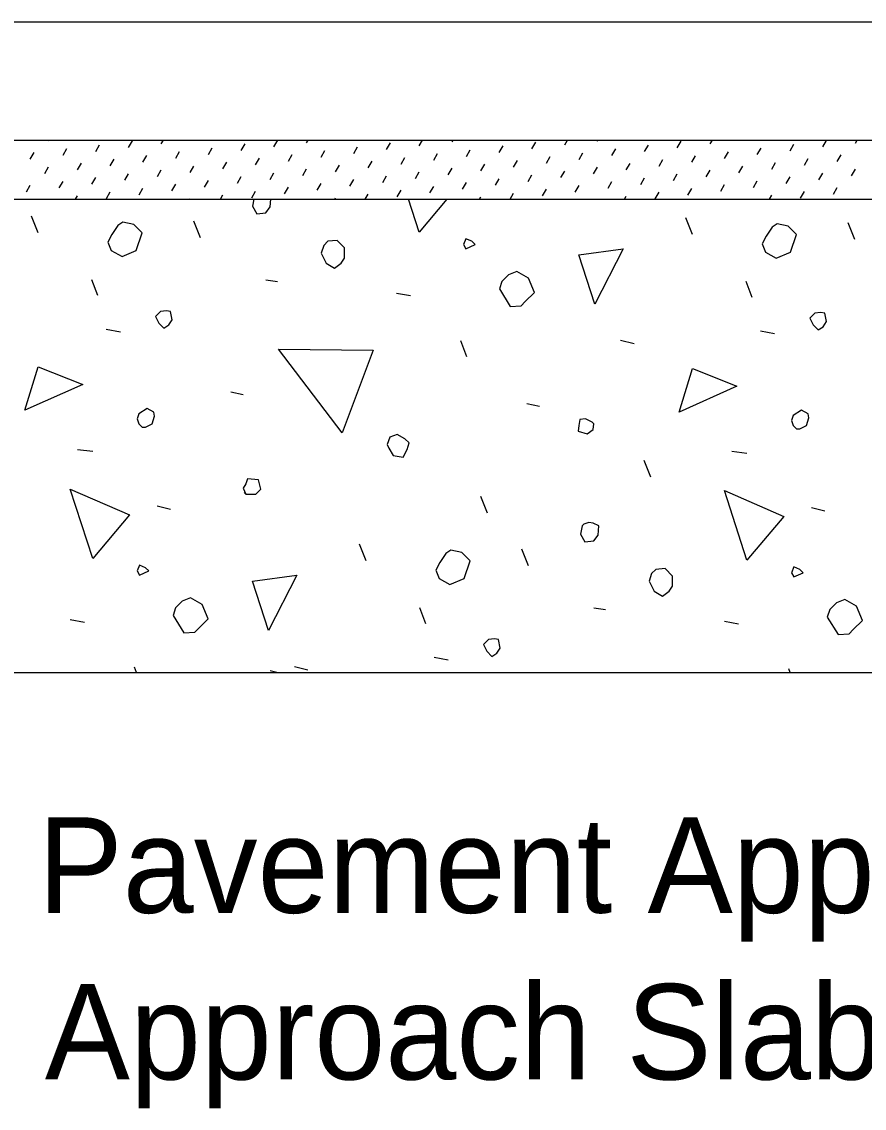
# Model space of a CAD drawing. Extents: x 130583.6 to 130653, y 88618.2 to 88652.9.
# Drawn here: x 130610.901 to 130612.682, y 88633.232 to 88635.527 of the extents above; entities that cross this region are included whole.
import ezdxf

# ---------------------------------------------------------------- set-up
doc = ezdxf.new("R2010")
doc.units = 0
for name, color, linetype in [('Dimension', 7, 'Continuous'), ('Miscellaneous', 7, 'Continuous'), ('TrafBarrierConc', 7, 'Continuous')]:
    doc.layers.add(name, color=color, linetype=linetype)

msp = doc.modelspace()

# ---------------------------------------------------------------- linework, layer by layer
at = {"layer": 'Miscellaneous'}
for p, q in [((130610.9581, 88635.2753), (130610.959, 88635.2768)), ((130611.127, 88635.2609), (130611.1351, 88635.2749)), ((130611.1961, 88635.269), (130611.2006, 88635.2768)), ((130611.4341, 88635.2628), (130611.4422, 88635.2768)), ((130611.5033, 88635.2709), (130611.5067, 88635.2768)), ((130611.7413, 88635.2647), (130611.7483, 88635.2768)), ((130611.8105, 88635.2728), (130611.8128, 88635.2768)), ((130611.9794, 88635.2585), (130611.9875, 88635.2725)), ((130612.0485, 88635.2666), (130612.0544, 88635.2768)), ((130612.1177, 88635.2747), (130612.1189, 88635.2768)), ((130612.2865, 88635.2604), (130612.2946, 88635.2743)), ((130612.3557, 88635.2685), (130612.3605, 88635.2768)), ((130612.4249, 88635.2766), (130612.425, 88635.2768)), ((130612.5937, 88635.2622), (130612.6018, 88635.2762)), ((130612.6629, 88635.2703), (130612.6666, 88635.2768)), ((130610.9195, 88635.2366), (130610.9276, 88635.2506)), ((130610.9886, 88635.2447), (130610.9967, 88635.2587)), ((130611.0578, 88635.2528), (130611.0659, 88635.2668)), ((130611.2267, 88635.2385), (130611.2348, 88635.2525)), ((130611.2958, 88635.2466), (130611.3039, 88635.2606)), ((130611.365, 88635.2547), (130611.3731, 88635.2687)), ((130611.5338, 88635.2404), (130611.5419, 88635.2544)), ((130611.603, 88635.2485), (130611.6111, 88635.2625)), ((130611.6722, 88635.2566), (130611.6803, 88635.2706)), ((130611.841, 88635.2423), (130611.8491, 88635.2563)), ((130611.9102, 88635.2504), (130611.9183, 88635.2644)), ((130612.0791, 88635.236), (130612.0872, 88635.25)), ((130612.1482, 88635.2441), (130612.1563, 88635.2581)), ((130612.2174, 88635.2523), (130612.2255, 88635.2662)), ((130612.3862, 88635.2379), (130612.3943, 88635.2519)), ((130612.4554, 88635.246), (130612.4635, 88635.26)), ((130612.5246, 88635.2541), (130612.5327, 88635.2681)), ((130611.0192, 88635.2142), (130611.0273, 88635.2282)), ((130611.0883, 88635.2223), (130611.0964, 88635.2363)), ((130611.1575, 88635.2304), (130611.1656, 88635.2444)), ((130611.3264, 88635.2161), (130611.3345, 88635.2301)), ((130611.3955, 88635.2242), (130611.4036, 88635.2382)), ((130611.4647, 88635.2323), (130611.4728, 88635.2463)), ((130611.6335, 88635.218), (130611.6416, 88635.232)), ((130611.7027, 88635.2261), (130611.7108, 88635.2401)), ((130611.7719, 88635.2342), (130611.78, 88635.2482)), ((130611.9407, 88635.2198), (130611.9488, 88635.2338)), ((130612.0099, 88635.2279), (130612.018, 88635.2419)), ((130612.1787, 88635.2136), (130612.1868, 88635.2276)), ((130612.2479, 88635.2217), (130612.256, 88635.2357)), ((130612.3171, 88635.2298), (130612.3252, 88635.2438)), ((130612.4859, 88635.2155), (130612.494, 88635.2295)), ((130612.5551, 88635.2236), (130612.5632, 88635.2376)), ((130612.6243, 88635.2317), (130612.6324, 88635.2457)), ((130610.95, 88635.2061), (130610.9581, 88635.2201)), ((130611.1189, 88635.1918), (130611.127, 88635.2058)), ((130611.188, 88635.1999), (130611.1961, 88635.2139)), ((130611.2572, 88635.208), (130611.2653, 88635.222)), ((130611.426, 88635.1937), (130611.4341, 88635.2077)), ((130611.4952, 88635.2018), (130611.5033, 88635.2158)), ((130611.5644, 88635.2099), (130611.5725, 88635.2239)), ((130611.7332, 88635.1955), (130611.7413, 88635.2095)), ((130611.8024, 88635.2036), (130611.8105, 88635.2176)), ((130611.8716, 88635.2117), (130611.8797, 88635.2257)), ((130611.9713, 88635.1893), (130611.9794, 88635.2033)), ((130612.0404, 88635.1974), (130612.0485, 88635.2114)), ((130612.1096, 88635.2055), (130612.1177, 88635.2195)), ((130612.2784, 88635.1912), (130612.2865, 88635.2052)), ((130612.3476, 88635.1993), (130612.3557, 88635.2133)), ((130612.4168, 88635.2074), (130612.4249, 88635.2214)), ((130612.5856, 88635.1931), (130612.5937, 88635.2071)), ((130612.6548, 88635.2012), (130612.6629, 88635.2152)), ((130610.9114, 88635.1675), (130610.9195, 88635.1815)), ((130610.9805, 88635.1756), (130610.9886, 88635.1896)), ((130611.0497, 88635.1837), (130611.0578, 88635.1977)), ((130611.2186, 88635.1693), (130611.2267, 88635.1833)), ((130611.2877, 88635.1775), (130611.2958, 88635.1914)), ((130611.3569, 88635.1856), (130611.365, 88635.1995)), ((130611.5257, 88635.1712), (130611.5338, 88635.1852)), ((130611.5949, 88635.1793), (130611.603, 88635.1933)), ((130611.6641, 88635.1874), (130611.6722, 88635.2014)), ((130611.8329, 88635.1731), (130611.841, 88635.1871)), ((130611.9021, 88635.1812), (130611.9102, 88635.1952)), ((130612.071, 88635.1669), (130612.0791, 88635.1809)), ((130612.1401, 88635.175), (130612.1482, 88635.189)), ((130612.2093, 88635.1831), (130612.2174, 88635.1971)), ((130612.3781, 88635.1688), (130612.3862, 88635.1828)), ((130612.4473, 88635.1769), (130612.4554, 88635.1909)), ((130612.5165, 88635.185), (130612.5246, 88635.199)), ((130611.0149, 88635.1518), (130611.0192, 88635.159)), ((130611.0802, 88635.1531), (130611.0883, 88635.1671)), ((130611.1494, 88635.1612), (130611.1575, 88635.1752)), ((130611.321, 88635.1518), (130611.3264, 88635.1609)), ((130611.3874, 88635.155), (130611.3955, 88635.169)), ((130611.4566, 88635.1631), (130611.4647, 88635.1771)), ((130611.6271, 88635.1518), (130611.6335, 88635.1628)), ((130611.6946, 88635.1569), (130611.7027, 88635.1709)), ((130611.7638, 88635.165), (130611.7719, 88635.179)), ((130611.9332, 88635.1518), (130611.9407, 88635.1647)), ((130612.0018, 88635.1588), (130612.0099, 88635.1728)), ((130612.1749, 88635.1518), (130612.1787, 88635.1584)), ((130612.2398, 88635.1526), (130612.2479, 88635.1666)), ((130612.309, 88635.1607), (130612.3171, 88635.1747)), ((130612.481, 88635.1518), (130612.4859, 88635.1603)), ((130612.547, 88635.1544), (130612.5551, 88635.1684)), ((130612.6162, 88635.1625), (130612.6243, 88635.1765)), ((130611.2566, 88635.1518), (130611.2572, 88635.1528)), ((130611.5627, 88635.1518), (130611.5644, 88635.1547)), ((130611.8688, 88635.1518), (130611.8716, 88635.1566)), ((130612.4165, 88635.1518), (130612.4168, 88635.1522)), ((130610.9364, 88635.0806), (130610.9223, 88635.116)), ((130612.3188, 88635.0771), (130612.3047, 88635.1125)), ((130611.2794, 88635.07), (130611.2652, 88635.1054)), ((130612.6618, 88635.0665), (130612.6476, 88635.1019)), ((130611.062, 88634.9481), (130611.0496, 88634.9816)), ((130611.4173, 88634.9816), (130611.442, 88634.9781)), ((130612.4443, 88634.9445), (130612.432, 88634.9781)), ((130611.693, 88634.9534), (130611.7231, 88634.9481)), ((130611.0796, 88634.8773), (130611.1097, 88634.872)), ((130612.462, 88634.8738), (130612.4921, 88634.8685)), ((130611.8415, 88634.819), (130611.8292, 88634.8526)), ((130612.1668, 88634.8544), (130612.1951, 88634.8473)), ((130611.343, 88634.7448), (130611.3695, 88634.7395)), ((130611.9688, 88634.72), (130611.9953, 88634.7147)), ((130611.0195, 88634.6228), (130611.0513, 88634.6193)), ((130612.4019, 88634.6193), (130612.4337, 88634.6157)), ((130612.2304, 88634.5645), (130612.2163, 88634.5998)), ((130611.8857, 88634.4884), (130611.8716, 88634.5238)), ((130611.1875, 88634.5043), (130611.2158, 88634.4973)), ((130612.5699, 88634.5008), (130612.5981, 88634.4937)), ((130611.6294, 88634.3877), (130611.6153, 88634.423)), ((130611.9724, 88634.3771), (130611.9582, 88634.4124)), ((130611.7549, 88634.2551), (130611.7425, 88634.2887)), ((130612.1102, 88634.2887), (130612.135, 88634.2851)), ((130611.0036, 88634.2639), (130611.0337, 88634.2586)), ((130612.386, 88634.2604), (130612.4161, 88634.2551)), ((130611.7726, 88634.1844), (130611.8026, 88634.1791)), ((130611.1439, 88634.1518), (130611.1397, 88634.1632)), ((130611.4261, 88634.1561), (130611.4435, 88634.1518)), ((130611.4774, 88634.1649), (130611.5057, 88634.1579)), ((130612.525, 88634.1518), (130612.5221, 88634.1596))]:
    msp.add_line(p, q, dxfattribs=at)
for points in [[(130611.389, 88635.1372), (130611.3978, 88635.1213), (130611.4173, 88635.1231), (130611.4261, 88635.1354), (130611.4276, 88635.1518)], [(130611.3919, 88635.1518), (130611.389, 88635.1372)], [(130611.7408, 88635.0824), (130611.7182, 88635.1518)], [(130611.7995, 88635.1518), (130611.7408, 88635.0824)], [(130611.0902, 88635.0435), (130611.1132, 88635.0311), (130611.1433, 88635.0435), (130611.1556, 88635.0806), (130611.138, 88635.0983), (130611.115, 88635.1036), (130611.1044, 88635.0965), (130611.092, 88635.0771), (130611.0832, 88635.0612), (130611.0902, 88635.0435)], [(130612.4726, 88635.04), (130612.4956, 88635.0276), (130612.5257, 88635.04), (130612.538, 88635.0771), (130612.5204, 88635.0948), (130612.4974, 88635.1001), (130612.4868, 88635.093), (130612.4744, 88635.0736), (130612.4656, 88635.0577), (130612.4726, 88635.04)], [(130611.8398, 88635.0471), (130611.8592, 88635.0559), (130611.8521, 88635.063), (130611.8398, 88635.0683), (130611.8345, 88635.0559), (130611.8398, 88635.0471)], [(130611.5339, 88635.0382), (130611.5446, 88635.017), (130611.5622, 88635.0064), (130611.5764, 88635.017), (130611.5834, 88635.0276), (130611.5834, 88635.0488), (130611.5675, 88635.0647), (130611.5481, 88635.063), (130611.5393, 88635.0541), (130611.5339, 88635.0382)], [(130612.112, 88634.9304), (130612.0784, 88635.0347), (130612.1721, 88635.0471), (130612.112, 88634.9304)], [(130611.9105, 88634.9622), (130611.9335, 88634.9251), (130611.9564, 88634.9268), (130611.9653, 88634.9357), (130611.9847, 88634.9551), (130611.9724, 88634.9852), (130611.9476, 88634.9993), (130611.9299, 88634.9923), (130611.9158, 88634.9781), (130611.9105, 88634.9622)], [(130611.191, 88634.8897), (130611.2016, 88634.8791), (130611.2122, 88634.8862), (130611.2193, 88634.8968), (130611.2158, 88634.9145), (130611.2069, 88634.9162), (130611.1945, 88634.9145), (130611.1839, 88634.9039), (130611.191, 88634.8897)], [(130612.5734, 88634.8862), (130612.584, 88634.8756), (130612.5946, 88634.8826), (130612.6017, 88634.8933), (130612.5981, 88634.9109), (130612.5893, 88634.9127), (130612.5769, 88634.9109), (130612.5663, 88634.9003), (130612.5734, 88634.8862)], [(130611.5781, 88634.6581), (130611.4438, 88634.8349), (130611.6436, 88634.8332), (130611.5781, 88634.6581)], [(130610.9082, 88634.7059), (130610.9364, 88634.7978), (130611.0301, 88634.7607), (130610.9082, 88634.7059)], [(130612.2906, 88634.7023), (130612.3188, 88634.7943), (130612.4125, 88634.7571), (130612.2906, 88634.7023)], [(130611.1556, 88634.6705), (130611.1627, 88634.6705), (130611.1769, 88634.6776), (130611.1822, 88634.6935), (130611.1804, 88634.7023), (130611.1663, 88634.7094), (130611.1486, 88634.6988), (130611.145, 88634.6882), (130611.1486, 88634.6776), (130611.1556, 88634.6705)], [(130612.538, 88634.667), (130612.5451, 88634.667), (130612.5593, 88634.6741), (130612.5646, 88634.69), (130612.5628, 88634.6988), (130612.5486, 88634.7059), (130612.531, 88634.6953), (130612.5274, 88634.6847), (130612.531, 88634.6741), (130612.538, 88634.667)], [(130612.0767, 88634.6617), (130612.0961, 88634.6564), (130612.1085, 88634.6652), (130612.1102, 88634.6776), (130612.1067, 88634.6811), (130612.0926, 88634.6882), (130612.0802, 88634.6864), (130612.0784, 88634.6741), (130612.0767, 88634.6617)], [(130611.6771, 88634.6263), (130611.686, 88634.6104), (130611.7072, 88634.6069), (130611.716, 88634.6228), (130611.7196, 88634.6369), (130611.7107, 88634.6458), (130611.6948, 88634.6546), (130611.6789, 88634.6493), (130611.6736, 88634.6334), (130611.6771, 88634.6263)], [(130611.3749, 88634.5291), (130611.3961, 88634.5291), (130611.4067, 88634.5397), (130611.4014, 88634.5591), (130611.3784, 88634.5609), (130611.3749, 88634.5503), (130611.3695, 88634.5415), (130611.3749, 88634.5291), (130611.3713, 88634.5326)], [(130611.0513, 88634.393), (130611.0036, 88634.5397), (130611.1291, 88634.4849), (130611.0513, 88634.393)], [(130612.4337, 88634.3894), (130612.386, 88634.5362), (130612.5115, 88634.4814), (130612.4337, 88634.3894)], [(130612.082, 88634.4442), (130612.0908, 88634.4283), (130612.1102, 88634.4301), (130612.1191, 88634.4425), (130612.1208, 88634.4619), (130612.1085, 88634.4672), (130612.0996, 88634.469), (130612.089, 88634.4655), (130612.0855, 88634.4619), (130612.082, 88634.4442)], [(130611.7832, 88634.3506), (130611.8062, 88634.3382), (130611.8362, 88634.3506), (130611.8486, 88634.3877), (130611.8309, 88634.4054), (130611.808, 88634.4107), (130611.7973, 88634.4036), (130611.785, 88634.3841), (130611.7761, 88634.3682), (130611.7832, 88634.3506)], [(130611.1503, 88634.3576), (130611.1698, 88634.3665), (130611.1627, 88634.3735), (130611.1503, 88634.3788), (130611.145, 88634.3665), (130611.1503, 88634.3576)], [(130611.4226, 88634.2409), (130611.389, 88634.3452), (130611.4827, 88634.3576), (130611.4226, 88634.2409)], [(130612.2269, 88634.3452), (130612.2375, 88634.324), (130612.2552, 88634.3134), (130612.2693, 88634.324), (130612.2764, 88634.3346), (130612.2764, 88634.3559), (130612.2605, 88634.3718), (130612.2411, 88634.37), (130612.2322, 88634.3612), (130612.2269, 88634.3452)], [(130612.5327, 88634.3541), (130612.5522, 88634.3629), (130612.5451, 88634.37), (130612.5327, 88634.3753), (130612.5274, 88634.3629), (130612.5327, 88634.3541)], [(130611.2211, 88634.2728), (130611.244, 88634.2356), (130611.267, 88634.2374), (130611.2759, 88634.2463), (130611.2953, 88634.2657), (130611.2829, 88634.2958), (130611.2582, 88634.3099), (130611.2405, 88634.3028), (130611.2264, 88634.2887), (130611.2211, 88634.2728)], [(130612.6034, 88634.2692), (130612.6264, 88634.2321), (130612.6494, 88634.2339), (130612.6582, 88634.2427), (130612.6777, 88634.2622), (130612.6653, 88634.2922), (130612.6406, 88634.3064), (130612.6229, 88634.2993), (130612.6088, 88634.2851), (130612.6034, 88634.2692)], [(130611.884, 88634.1968), (130611.8946, 88634.1861), (130611.9052, 88634.1932), (130611.9123, 88634.2038), (130611.9087, 88634.2215), (130611.8999, 88634.2233), (130611.8875, 88634.2215), (130611.8769, 88634.2109), (130611.884, 88634.1968)]]:
    msp.add_lwpolyline(points, dxfattribs=at)
at = {"layer": 'TrafBarrierConc'}
for p, q in [((130607.6086, 88635.5268), (130620.4397, 88635.5268)), ((130607.6086, 88635.2768), (130623.4397, 88635.2768)), ((130607.6087, 88635.1518), (130623.4398, 88635.1518)), ((130607.6086, 88634.1518), (130623.4397, 88634.1518))]:
    msp.add_line(p, q, dxfattribs=at)

# ---------------------------------------------------------------- texts
at = {"layer": 'Dimension'}
for s, p in [('Approach Slab (Flexible Pavement Approach Slab ', (130607.9981, 88633.6444)), ('Shown, Rigid Pavement Approach Slab Similar, Typ.) ', (130607.9981, 88633.2924))]:
    msp.add_text(s, height=0.2016, dxfattribs=at).set_placement(p)

doc.saveas('drawing.dxf')
